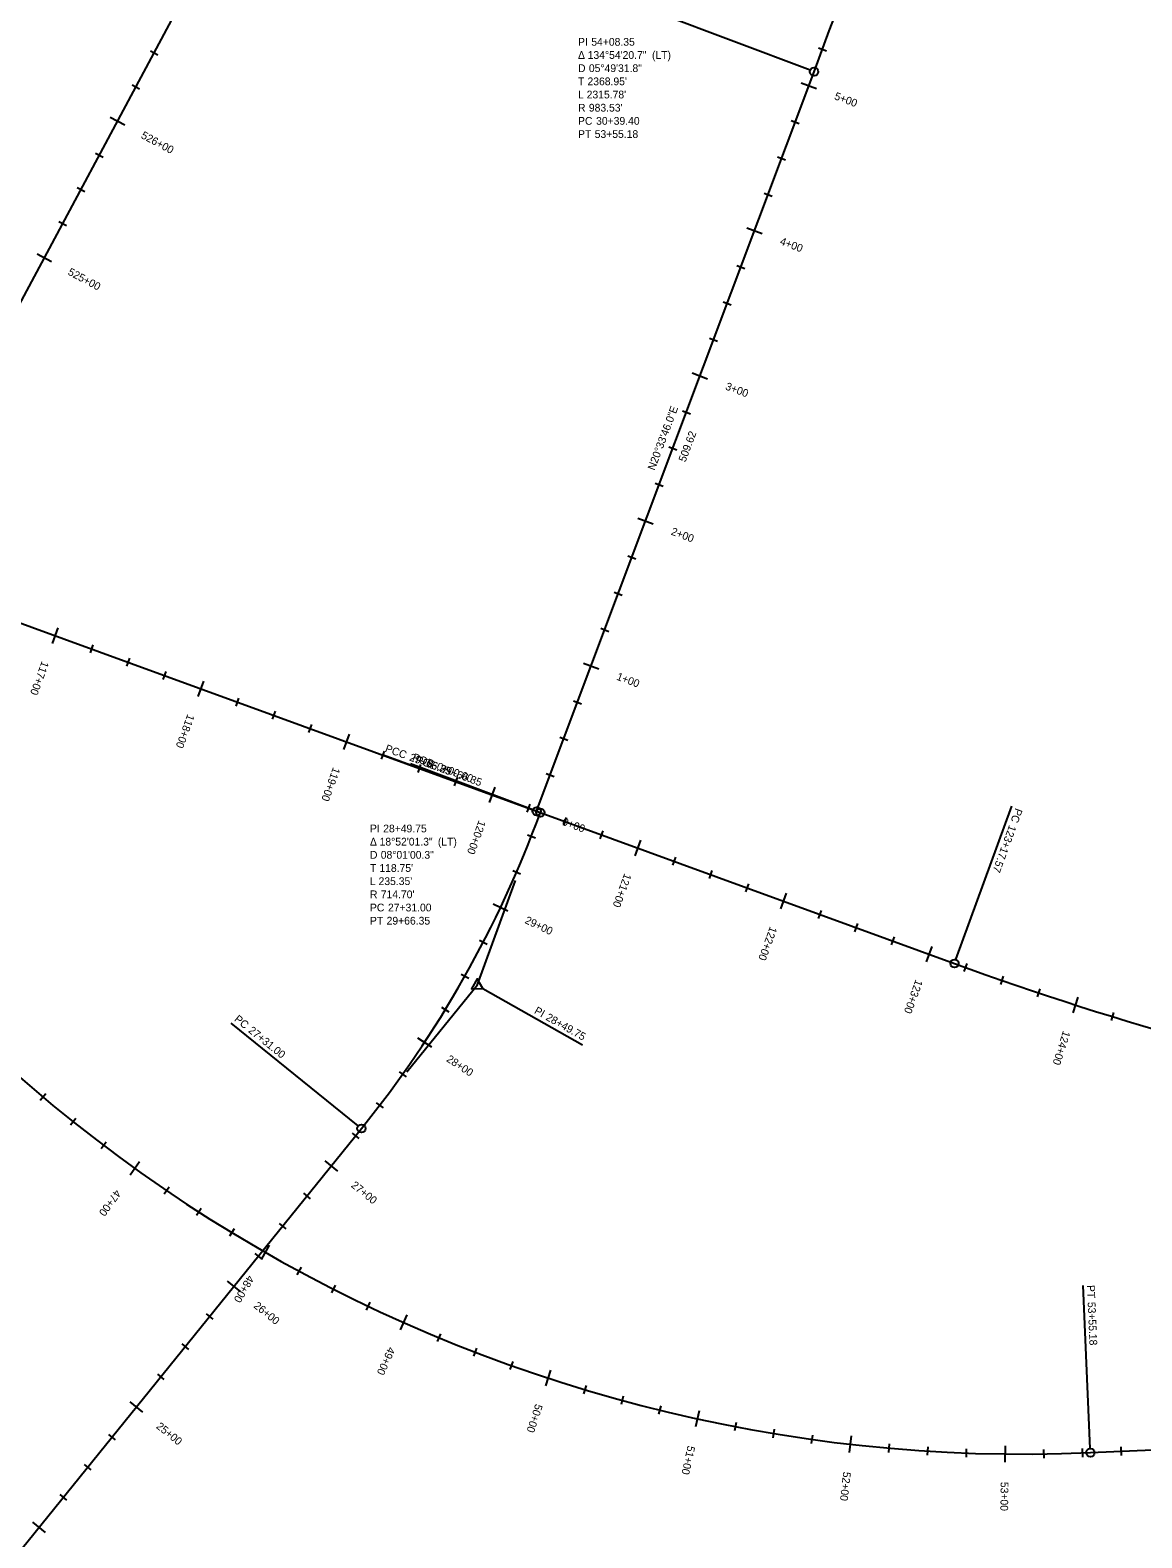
# Model space of a CAD drawing. Extents: x 2300830 to 2307917, y 756066 to 766359.
# Drawn here: x 2303529 to 2304246, y 760655 to 761628 of the extents above; entities that cross this region are included whole.
import ezdxf

# ---------------------------------------------------------------- set-up
doc = ezdxf.new("R2010")
doc.units = 0
for name, color, linetype in [('Default', 7, 'Continuous'), ('Draft_Bearing Label', 7, 'Continuous'), ('Draft_Curve Data Label', 7, 'Continuous'), ('Draft_Station Cardinal Lines', 7, 'Continuous'), ('Draft_Station Cardinal Points', 7, 'Continuous'), ('Draft_Station Labels Major', 7, 'Continuous'), ('Draft_Station Ticks Major', 7, 'Continuous'), ('Draft_Station Ticks Minor', 7, 'Continuous'), ('Geom_Baseline', 7, 'Continuous')]:
    doc.layers.add(name, color=color, linetype=linetype)

msp = doc.modelspace()

# ---------------------------------------------------------------- linework, layer by layer
at = {"layer": 'Default'}
for p, q in [((2301469.01, 757616.61), (2303797.09, 761964.97)), ((2301469.01, 757616.61), (2303797.09, 761964.97)), ((2303855.74, 761124.3), (2304034.74, 761601.45)), ((2302574.77, 761591.29), (2304125.31, 761026.02)), ((2302671.51, 759594.38), (2303742.71, 760919.55)), ((2304212.98, 760710.44), (2305828.49, 760781.61))]:
    msp.add_line(p, q, dxfattribs=at)
for centre, radius, start, end in [((2304169.7, 761693.02), 983.53, 137.61666, 272.52241), ((2298662.99, 763616.57), 5737.28, 339.437219, 345.42872), ((2303616.31, 761265.54), 714.7, 64.28167, 164.6807), ((2303186.89, 761368.85), 714.7, 321.04981, 339.91683), ((2304854.63, 763026.57), 2129.34, 249.97011, 268.33163)]:
    msp.add_arc(centre, radius, start, end, dxfattribs=at)
at = {"layer": 'Draft_Station Cardinal Lines'}
for p, q in [((2304032.24, 761602.39), (2303933.62, 761639.38)), ((2303855.62, 761124.35), (2303756.7, 761160.52)), ((2304126.23, 761028.53), (2304162.3, 761127.49)), ((2303817.36, 761011.9), (2303842.08, 761079.53)), ((2303817.36, 761011.9), (2303772.09, 760955.91)), ((2303821.01, 761009.83), (2303885.23, 760973.47)), ((2303740.63, 760921.23), (2303658.72, 760987.45)), ((2304212.87, 760713.11), (2304208.23, 760818.33))]:
    msp.add_line(p, q, dxfattribs=at)
msp.add_lwpolyline([(2303820.97, 761009.86), (2303817.32, 761016.06), (2303813.77, 761009.79)], close=True, dxfattribs=at)
at = {"layer": 'Draft_Station Cardinal Points'}
for p, q in [((2304034.74, 761601.45), (2304034.74, 761601.45)), ((2303756.7, 761160.52), (2303756.7, 761160.52)), ((2303853.24, 761125.23), (2303774.29, 761154.85)), ((2303774.29, 761154.85), (2303792.71, 761147.94)), ((2303855.62, 761124.35), (2303776.42, 761153.3)), ((2303776.42, 761153.3), (2303794.91, 761146.55)), ((2303855.74, 761124.3), (2303855.74, 761124.3)), ((2303858.13, 761123.43), (2303858.13, 761123.43)), ((2304162.3, 761127.49), (2304162.3, 761127.49)), ((2304125.31, 761026.02), (2304125.31, 761026.02)), ((2303817.36, 761011.9), (2303817.36, 761011.9)), ((2303658.72, 760987.45), (2303658.72, 760987.45)), ((2303885.23, 760973.47), (2303885.23, 760973.47)), ((2303742.71, 760919.55), (2303742.71, 760919.55)), ((2304208.23, 760818.33), (2304208.23, 760818.33)), ((2304212.98, 760710.44), (2304212.98, 760710.44))]:
    msp.add_line(p, q, dxfattribs=at)
for centre in [(2304034.74, 761601.45), (2303855.74, 761124.3), (2303858.13, 761123.43), (2304125.31, 761026.02), (2303742.71, 760919.55), (2304212.98, 760710.44)]:
    msp.add_circle(centre, 2.67, dxfattribs=at)
at = {"layer": 'Draft_Station Ticks Major'}
for p, q in [((2304026.36, 761594.31), (2304036.3, 761590.58)), ((2303580.71, 761572.12), (2303590.07, 761567.1)), ((2303991.24, 761500.69), (2304001.18, 761496.96)), ((2303533.51, 761483.96), (2303542.87, 761478.94)), ((2303956.11, 761407.06), (2303966.06, 761403.33)), ((2303920.99, 761313.43), (2303930.93, 761309.7)), ((2303546.93, 761242.56), (2303543.29, 761232.59)), ((2303885.87, 761219.8), (2303895.81, 761216.07)), ((2303640.88, 761208.31), (2303637.24, 761198.34)), ((2303734.83, 761174.06), (2303731.19, 761164.08)), ((2303828.78, 761139.81), (2303825.15, 761129.83)), ((2303850.74, 761126.17), (2303860.69, 761122.44)), ((2303922.73, 761105.56), (2303919.1, 761095.58)), ((2303827.67, 761064.55), (2303837.26, 761060)), ((2304016.69, 761071.31), (2304013.05, 761061.33)), ((2304110.64, 761037.06), (2304107, 761027.08)), ((2304204.92, 761004.38), (2304201.67, 760994.27)), ((2303778.97, 760978.16), (2303787.83, 760972.31)), ((2303599.64, 760898.1), (2303593.45, 760889.47)), ((2303719.06, 760898.8), (2303727.32, 760892.12)), ((2303683.27, 760844.35), (2303677.98, 760835.13)), ((2303656.2, 760821.03), (2303664.46, 760814.35)), ((2303771.92, 760799.36), (2303767.6, 760789.65)), ((2303864.68, 760763.6), (2303861.37, 760753.51)), ((2303593.33, 760743.26), (2303601.59, 760736.59)), ((2303960.59, 760737.44), (2303958.32, 760727.06)), ((2304058.66, 760721.15), (2304057.45, 760710.6)), ((2304157.88, 760714.9), (2304157.75, 760704.28)), ((2303530.47, 760665.49), (2303538.73, 760658.82))]:
    msp.add_line(p, q, dxfattribs=at)
at = {"layer": 'Draft_Station Ticks Minor'}
for p, q in [((2303606.58, 761614.98), (2303611.45, 761612.37)), ((2304037.54, 761616.82), (2304042.71, 761614.89)), ((2303594.78, 761592.94), (2303599.65, 761590.33)), ((2304020, 761570), (2304025.16, 761568.06)), ((2303571.18, 761548.86), (2303576.05, 761546.25)), ((2304011.22, 761546.59), (2304016.38, 761544.66)), ((2303559.38, 761526.82), (2303564.25, 761524.21)), ((2304002.43, 761523.19), (2304007.6, 761521.25)), ((2303547.58, 761504.78), (2303552.45, 761502.17)), ((2303984.87, 761476.37), (2303990.04, 761474.43)), ((2303976.09, 761452.97), (2303981.26, 761451.03)), ((2303967.31, 761429.56), (2303972.48, 761427.62)), ((2303949.75, 761382.74), (2303954.92, 761380.8)), ((2303940.97, 761359.34), (2303946.14, 761357.4)), ((2303932.19, 761335.93), (2303937.36, 761333.99)), ((2303914.63, 761289.11), (2303919.79, 761287.18)), ((2303905.85, 761265.71), (2303911.01, 761263.77)), ((2303897.06, 761242.3), (2303902.23, 761240.36)), ((2303569.53, 761231.58), (2303567.64, 761226.39)), ((2303593.02, 761223.01), (2303591.13, 761217.83)), ((2303616.51, 761214.45), (2303614.62, 761209.27)), ((2303663.48, 761197.33), (2303661.59, 761192.14)), ((2303879.5, 761195.49), (2303884.67, 761193.55)), ((2303686.97, 761188.76), (2303685.08, 761183.58)), ((2303710.46, 761180.2), (2303708.57, 761175.01)), ((2303870.72, 761172.08), (2303875.89, 761170.14)), ((2303757.44, 761163.08), (2303755.55, 761157.89)), ((2303780.92, 761154.51), (2303779.03, 761149.33)), ((2303804.41, 761145.95), (2303802.52, 761140.76)), ((2303861.94, 761148.67), (2303867.11, 761146.73)), ((2303851.39, 761128.82), (2303849.5, 761123.64)), ((2303874.88, 761120.26), (2303872.98, 761115.08)), ((2303849.77, 761109.15), (2303854.91, 761107.13)), ((2303898.36, 761111.7), (2303896.47, 761106.51)), ((2303945.34, 761094.57), (2303943.45, 761089.39)), ((2303840.29, 761086.12), (2303845.35, 761083.93)), ((2303968.83, 761086.01), (2303966.94, 761080.82)), ((2303992.31, 761077.45), (2303990.42, 761072.26)), ((2304039.29, 761060.32), (2304037.4, 761055.14)), ((2304062.78, 761051.76), (2304060.89, 761046.57)), ((2303818.92, 761041.14), (2303823.83, 761038.6)), ((2304086.27, 761043.2), (2304084.38, 761038.01)), ((2304133.24, 761026.09), (2304131.36, 761020.89)), ((2303807.08, 761019.24), (2303811.89, 761016.53)), ((2304156.77, 761017.75), (2304154.96, 761012.54)), ((2304180.41, 761009.7), (2304178.66, 761004.46)), ((2303794.47, 760997.76), (2303799.18, 760994.89)), ((2304227.95, 760994.43), (2304226.32, 760989.15)), ((2303767.05, 760956.2), (2303771.54, 760953)), ((2303539.08, 760941.86), (2303535.53, 760937.63)), ((2303752.26, 760936.16), (2303756.64, 760932.81)), ((2303558.37, 760926.08), (2303554.93, 760921.76)), ((2303578.06, 760910.79), (2303574.73, 760906.39)), ((2303736.79, 760916.62), (2303741.08, 760913.15)), ((2303618.58, 760881.73), (2303615.47, 760877.17)), ((2303705.35, 760877.74), (2303709.65, 760874.27)), ((2303639.37, 760867.99), (2303636.39, 760863.35)), ((2303660.51, 760854.78), (2303657.65, 760850.06)), ((2303689.64, 760858.29), (2303693.93, 760854.82)), ((2303673.92, 760838.85), (2303678.21, 760835.38)), ((2303703.77, 760829.99), (2303701.14, 760825.13)), ((2303725.85, 760818.42), (2303723.35, 760813.5)), ((2303748.22, 760807.42), (2303745.85, 760802.44)), ((2303642.49, 760799.97), (2303646.78, 760796.5)), ((2303793.77, 760787.15), (2303791.65, 760782.05)), ((2303626.77, 760780.52), (2303631.07, 760777.05)), ((2303816.92, 760777.89), (2303814.93, 760772.74)), ((2303840.29, 760769.22), (2303838.43, 760764.02)), ((2303611.06, 760761.08), (2303615.35, 760757.61)), ((2303887.66, 760753.67), (2303886.07, 760748.39)), ((2303911.62, 760746.81), (2303910.17, 760741.48)), ((2303935.75, 760740.56), (2303934.44, 760735.19)), ((2303984.46, 760729.9), (2303983.41, 760724.48)), ((2304008.99, 760725.5), (2304008.09, 760720.06)), ((2303579.63, 760722.2), (2303583.92, 760718.73)), ((2304033.64, 760721.73), (2304032.87, 760716.26)), ((2304083.17, 760716.07), (2304082.68, 760710.57)), ((2304108.03, 760714.19), (2304107.68, 760708.68)), ((2304232.66, 760714.07), (2304232.9, 760708.55)), ((2304132.92, 760712.94), (2304132.72, 760707.42)), ((2304182.78, 760712.33), (2304182.85, 760706.81)), ((2304207.7, 760712.98), (2304207.91, 760707.47)), ((2303563.91, 760702.76), (2303568.2, 760699.29)), ((2303548.19, 760683.31), (2303552.49, 760679.84))]:
    msp.add_line(p, q, dxfattribs=at)
at = {"layer": 'Geom_Baseline'}
for p, q in [((2301469.01, 757616.61), (2303797.09, 761964.97)), ((2303855.74, 761124.3), (2304034.74, 761601.45)), ((2302574.77, 761591.29), (2304125.31, 761026.02)), ((2302671.51, 759594.38), (2303742.71, 760919.55)), ((2304212.98, 760710.44), (2305828.49, 760781.61))]:
    msp.add_line(p, q, dxfattribs=at)
for centre, radius, start, end in [((2304169.7, 761693.02), 983.53, 137.61666, 272.52241), ((2298662.99, 763616.57), 5737.28, 339.437219, 345.42872), ((2303616.31, 761265.54), 714.7, 64.28167, 164.6807), ((2303186.89, 761368.85), 714.7, 321.04981, 339.91683), ((2304854.63, 763026.57), 2129.34, 249.97011, 268.33163)]:
    msp.add_arc(centre, radius, start, end, dxfattribs=at)

# ---------------------------------------------------------------- texts
at = {"layer": 'Draft_Bearing Label'}
for s, p in [('N20°33\'46.0"E', (2303931.82, 761343.84)), ('509.62', (2303951.74, 761349.23))]:
    msp.add_text(s, height=5, rotation=69.43722, dxfattribs=at).set_placement(p)
at = {"layer": 'Draft_Curve Data Label'}
for s, p in [('PI ', (2303882.44, 761618.23)), ('54+08.35', (2303890.98, 761618.23)), ('Δ ', (2303882.44, 761609.73)), ('134°54\'20.7"', (2303888.66, 761609.73)), (' (LT)', (2303928.28, 761609.73)), ('D ', (2303882.44, 761601.23)), ('05°49\'31.8"', (2303889.43, 761601.23)), ('T ', (2303882.44, 761592.73)), ("2368.95'", (2303888.53, 761592.73)), ('L ', (2303882.44, 761584.23)), ('R ', (2303882.44, 761575.73)), ("2315.78'", (2303888.01, 761584.23)), ("983.53'", (2303889.43, 761575.73)), ('PC ', (2303882.44, 761567.23)), ('30+39.40', (2303894.09, 761567.23)), ('PT ', (2303882.44, 761558.73)), ('53+55.18', (2303893.19, 761558.73)), ('PI ', (2303748.21, 761110.64)), ('28+49.75', (2303756.75, 761110.64)), ('Δ ', (2303748.21, 761102.14)), ('18°52\'01.3"', (2303754.43, 761102.14)), (' (LT)', (2303790.16, 761102.14)), ('D ', (2303748.21, 761093.64)), ('08°01\'00.3"', (2303755.19, 761093.64)), ('T ', (2303748.21, 761085.14)), ("118.75'", (2303754.29, 761085.14)), ('L ', (2303748.21, 761076.64)), ("235.35'", (2303753.77, 761076.64)), ('R ', (2303748.21, 761068.14)), ('PC ', (2303748.21, 761059.64)), ("714.70'", (2303755.19, 761068.14)), ('27+31.00', (2303759.85, 761059.64)), ('PT ', (2303748.21, 761051.14)), ('29+66.35', (2303758.95, 761051.14))]:
    msp.add_text(s, height=5, dxfattribs=at).set_placement(p)
at = {"layer": 'Draft_Station Cardinal Points'}
for s, rotation, p in [('PCC', 339.91683, (2303757.55, 761162.85)), ('POB ', 339.43722, (2303775.16, 761157.18)), ('29+66.35', 339.91683, (2303773.23, 761157.12)), ('POE ', 339.91683, (2303777.28, 761155.64)), ('0+00.00', 339.43722, (2303790.79, 761151.31)), ('29+66.35', 339.91683, (2303792.96, 761149.9)), ('PC', 249.97011, (2304164.64, 761126.64)), ('123+17.57', 249.97011, (2304160.65, 761115.7)), ('PI ', 330.48332, (2303853.75, 760994.15)), ('PC', 321.04981, (2303660.28, 760989.38)), ('28+49.75', 330.48332, (2303861.19, 760989.94)), ('27+31.00', 321.04981, (2303669.33, 760982.06)), ('PT', 272.52241, (2304210.71, 760818.44)), ('53+55.18', 272.52241, (2304211.19, 760807.58))]:
    msp.add_text(s, height=5, rotation=rotation, dxfattribs=at).set_placement(p)
at = {"layer": 'Draft_Station Labels Major'}
for s, rotation, p in [('5+00', 339.43722, (2304047.34, 761583.78)), ('526+00', 331.8357, (2303600.1, 761558.89)), ('4+00', 339.43722, (2304012.21, 761490.15)), ('525+00', 331.8357, (2303552.9, 761470.73)), ('3+00', 339.43722, (2303977.09, 761396.52)), ('2+00', 339.43722, (2303941.97, 761302.89)), ('117+00', 249.97011, (2303536.59, 761221.49)), ('1+00', 339.43722, (2303906.84, 761209.26)), ('118+00', 249.97011, (2303630.54, 761187.24)), ('119+00', 249.97011, (2303724.49, 761152.99)), ('120+00', 249.97011, (2303818.44, 761118.74)), ('0+00', 339.43722, (2303871.72, 761115.63)), ('121+00', 249.97011, (2303912.39, 761084.49)), ('29+00', 334.59785, (2303847.68, 761052.28)), ('122+00', 249.97011, (2304006.34, 761050.24)), ('123+00', 249.97011, (2304100.29, 761015.99)), ('124+00', 252.18824, (2304195.4, 760982.92)), ('28+00', 326.58111, (2303797.07, 760963.22)), ('47+00', 234.35463, (2303584.01, 760880.59)), ('27+00', 321.04981, (2303735.64, 760882.18)), ('48+00', 240.18013, (2303669.49, 760825.34)), ('26+00', 321.04981, (2303672.78, 760804.41)), ('49+00', 246.00563, (2303760.14, 760779.05)), ('50+00', 251.83113, (2303855.02, 760742.2)), ('25+00', 321.04981, (2303609.91, 760726.64)), ('51+00', 257.65663, (2303953.16, 760715.17)), ('52+00', 263.48213, (2304053.53, 760698.24)), ('53+00', 269.30763, (2304155.1, 760691.59))]:
    msp.add_text(s, height=5, rotation=rotation, dxfattribs=at).set_placement(p)

doc.saveas('drawing.dxf')
